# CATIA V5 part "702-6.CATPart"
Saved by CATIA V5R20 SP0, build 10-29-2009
Part number: 702-6
Source: Unknown
Property "ARTICLENO": "702-6"
Property "BOMINFO": "702-6"
Property "CODE": "702-6"
Property "L": "180.000"
Property "LINA": "702-6"
Property "NB": "702-6"
Property "NBSYN": "$CODE."
Property "NN": "702"
Property "SUPPLIER": "CF"
Bounding box of the stored display mesh (mm): x -107 to 0, y 0 to 180, z -15 to 15
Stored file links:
  C:\Users\Utente\Desktop\3D files 702\702-6.CATPart
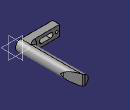
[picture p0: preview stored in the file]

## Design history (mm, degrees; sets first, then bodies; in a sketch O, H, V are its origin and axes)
Body1 "Geometry.1" (main body)
  Solid1 "702-6.catpart": solid without history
